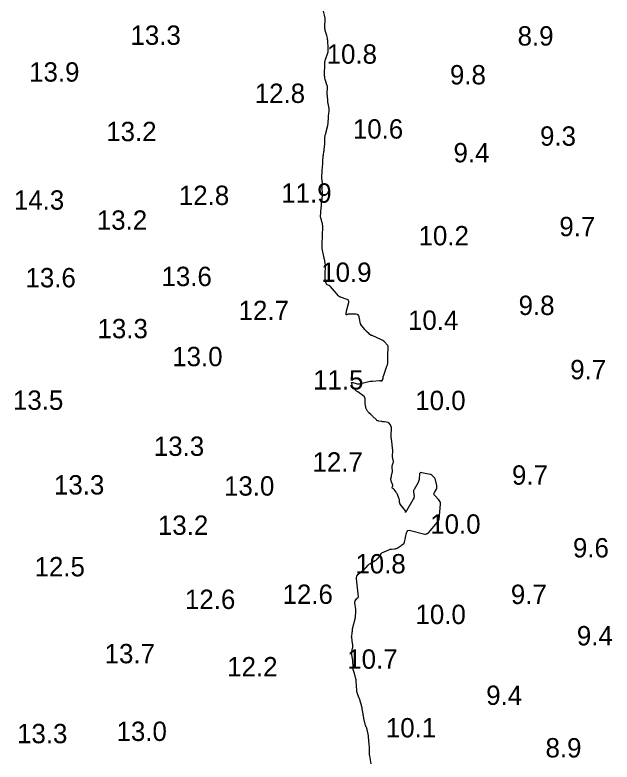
# Model space of a CAD drawing. Extents: x 815352 to 820877, y 582403 to 597439.
# Drawn here: x 820644.3 to 820798.6, y 590619.8 to 590813 of the extents above; entities that cross this region are included whole.
import ezdxf

# ---------------------------------------------------------------- set-up
doc = ezdxf.new("R2010")
doc.units = 0
doc.layers.add('V-CONT-EL12', color=7, linetype='Continuous')
doc.layers.add('V-TOPO-SOUN', color=7, linetype='Continuous')

msp = doc.modelspace()

# ---------------------------------------------------------------- linework, layer by layer
at = {"layer": 'V-CONT-EL12'}
msp.add_lwpolyline([(820736.39, 590619.34), (820735.98, 590621.46), (820735.95, 590621.62), (820735.93, 590621.77), (820735.92, 590621.93), (820735.92, 590622.08), (820735.92, 590622.71), (820735.92, 590622.86), (820735.91, 590623.02), (820735.91, 590623.17), (820735.9, 590623.33), (820735.8, 590624.67), (820735.78, 590624.87), (820735.77, 590625.07), (820735.75, 590625.27), (820735.74, 590625.47), (820735.67, 590626.26), (820735.65, 590626.46), (820735.63, 590626.65), (820735.6, 590626.85), (820735.56, 590627.04), (820735.34, 590628.15), (820735.31, 590628.25), (820735.28, 590628.35), (820735.25, 590628.45), (820735.21, 590628.55), (820735.04, 590628.93), (820735, 590629.03), (820734.97, 590629.12), (820734.94, 590629.22), (820734.91, 590629.32), (820734.49, 590631.05), (820734.42, 590631.35), (820734.35, 590631.65), (820734.3, 590631.95), (820734.24, 590632.26), (820734.03, 590633.59), (820733.99, 590633.83), (820733.94, 590634.08), (820733.89, 590634.32), (820733.83, 590634.55), (820733.55, 590635.57), (820733.49, 590635.78), (820733.43, 590635.98), (820733.36, 590636.18), (820733.28, 590636.38), (820732.86, 590637.43), (820732.83, 590637.5), (820732.81, 590637.57), (820732.78, 590637.64), (820732.76, 590637.72), (820732.67, 590638.01), (820732.65, 590638.09), (820732.64, 590638.16), (820732.62, 590638.24), (820732.62, 590638.32), (820732.47, 590640.7), (820732.47, 590640.76), (820732.47, 590640.81), (820732.46, 590640.87), (820732.46, 590640.92), (820732.44, 590641.14), (820732.44, 590641.2), (820732.43, 590641.25), (820732.42, 590641.31), (820732.41, 590641.36), (820732.21, 590642.12), (820732.17, 590642.27), (820732.13, 590642.41), (820732.08, 590642.55), (820732.04, 590642.69), (820731.76, 590643.53), (820731.74, 590643.62), (820731.72, 590643.71), (820731.71, 590643.8), (820731.7, 590643.9), (820731.69, 590644.27), (820731.69, 590644.37), (820731.68, 590644.46), (820731.68, 590644.55), (820731.67, 590644.65), (820731.61, 590645.83), (820731.59, 590646.03), (820731.57, 590646.23), (820731.55, 590646.43), (820731.51, 590646.63), (820731.35, 590647.52), (820731.32, 590647.67), (820731.31, 590647.82), (820731.31, 590647.97), (820731.33, 590648.12), (820731.42, 590648.92), (820731.43, 590648.98), (820731.44, 590649.03), (820731.46, 590649.09), (820731.49, 590649.14), (820731.6, 590649.35), (820731.62, 590649.41), (820731.63, 590649.46), (820731.64, 590649.52), (820731.64, 590649.58), (820731.59, 590650.05), (820731.58, 590650.15), (820731.57, 590650.25), (820731.56, 590650.35), (820731.54, 590650.45), (820731.32, 590652.01), (820731.3, 590652.14), (820731.3, 590652.27), (820731.31, 590652.4), (820731.33, 590652.53), (820731.43, 590653.07), (820731.45, 590653.2), (820731.47, 590653.32), (820731.48, 590653.45), (820731.49, 590653.57), (820731.53, 590654.08), (820731.54, 590654.21), (820731.56, 590654.33), (820731.58, 590654.46), (820731.61, 590654.58), (820732.2, 590656.85), (820732.24, 590657.05), (820732.28, 590657.24), (820732.3, 590657.44), (820732.32, 590657.64), (820732.37, 590658.43), (820732.37, 590658.63), (820732.37, 590658.83), (820732.36, 590659.03), (820732.35, 590659.23), (820732.14, 590661.02), (820732.14, 590661.14), (820732.15, 590661.25), (820732.19, 590661.37), (820732.24, 590661.47), (820732.57, 590662), (820732.61, 590662.05), (820732.65, 590662.1), (820732.7, 590662.14), (820732.75, 590662.18), (820732.96, 590662.32), (820733, 590662.36), (820733.03, 590662.41), (820733.05, 590662.46), (820733.05, 590662.52), (820732.54, 590667.23), (820732.55, 590667.57), (820732.62, 590667.87), (820732.78, 590668.14), (820733.01, 590668.37), (820734.27, 590669.4), (820734.45, 590669.55), (820734.63, 590669.71), (820734.8, 590669.88), (820734.96, 590670.04), (820735.61, 590670.73), (820735.77, 590670.9), (820735.95, 590671.05), (820736.14, 590671.19), (820736.34, 590671.31), (820737.39, 590671.91), (820737.54, 590672.01), (820737.69, 590672.12), (820737.83, 590672.24), (820737.96, 590672.37), (820738.58, 590673.06), (820738.63, 590673.13), (820738.68, 590673.2), (820738.73, 590673.28), (820738.77, 590673.36), (820738.92, 590673.69), (820738.96, 590673.76), (820739.01, 590673.83), (820739.08, 590673.88), (820739.15, 590673.92), (820740.93, 590674.73), (820741.1, 590674.79), (820741.28, 590674.84), (820741.46, 590674.88), (820741.64, 590674.9), (820742.38, 590674.93), (820742.57, 590674.95), (820742.74, 590675), (820742.91, 590675.06), (820743.07, 590675.15), (820744.15, 590675.85), (820744.23, 590675.9), (820744.31, 590675.96), (820744.39, 590676.02), (820744.47, 590676.08), (820744.77, 590676.33), (820744.84, 590676.4), (820744.9, 590676.48), (820744.94, 590676.56), (820744.97, 590676.65), (820745.49, 590679.06), (820745.62, 590679.42), (820745.84, 590679.65), (820746.15, 590679.75), (820746.53, 590679.7), (820750.19, 590678.76), (820750.24, 590678.76), (820750.28, 590678.75), (820750.33, 590678.76), (820750.38, 590678.76), (820750.62, 590678.83), (820750.64, 590678.83), (820750.65, 590678.84), (820750.67, 590678.84), (820750.69, 590678.84), (820750.76, 590678.85), (820750.78, 590678.86), (820750.8, 590678.86), (820750.82, 590678.87), (820750.83, 590678.88), (820751.03, 590678.99), (820751.06, 590679.01), (820751.1, 590679.04), (820751.13, 590679.07), (820751.16, 590679.1), (820753.52, 590681.87), (820753.55, 590681.9), (820753.58, 590681.93), (820753.6, 590681.97), (820753.63, 590682), (820753.73, 590682.15), (820753.75, 590682.18), (820753.76, 590682.22), (820753.78, 590682.25), (820753.8, 590682.28), (820753.87, 590682.41), (820753.89, 590682.45), (820753.9, 590682.48), (820753.91, 590682.52), (820753.91, 590682.55), (820754.26, 590686.48), (820754.26, 590686.81), (820754.19, 590687.11), (820754.05, 590687.39), (820753.85, 590687.65), (820752.78, 590688.76), (820752.65, 590688.94), (820752.59, 590689.13), (820752.61, 590689.33), (820752.7, 590689.54), (820753.2, 590690.38), (820753.3, 590690.59), (820753.36, 590690.81), (820753.37, 590691.04), (820753.34, 590691.28), (820752.98, 590692.78), (820752.93, 590692.93), (820752.87, 590693.07), (820752.79, 590693.19), (820752.69, 590693.32), (820752.11, 590693.94), (820752.08, 590693.97), (820752.04, 590694), (820752, 590694.03), (820751.97, 590694.05), (820751.8, 590694.14), (820751.76, 590694.16), (820751.72, 590694.18), (820751.68, 590694.19), (820751.63, 590694.2), (820749.41, 590694.63), (820749.17, 590694.64), (820749, 590694.57), (820748.89, 590694.42), (820748.85, 590694.19), (820748.8, 590693.11), (820748.77, 590692.85), (820748.71, 590692.59), (820748.62, 590692.34), (820748.5, 590692.1), (820747.43, 590690.32), (820747.36, 590690.18), (820747.32, 590690.03), (820747.3, 590689.88), (820747.31, 590689.73), (820747.41, 590688.95), (820747.42, 590688.87), (820747.42, 590688.78), (820747.43, 590688.7), (820747.43, 590688.61), (820747.42, 590688.23), (820747.42, 590688.17), (820747.4, 590688.11), (820747.38, 590688.06), (820747.36, 590688.01), (820747.23, 590687.8), (820747.2, 590687.75), (820747.17, 590687.69), (820747.14, 590687.64), (820747.11, 590687.59), (820745.5, 590684.8), (820745.43, 590684.69), (820745.36, 590684.58), (820745.28, 590684.48), (820745.19, 590684.38), (820745.26, 590684.48), (820745.28, 590684.57), (820745.27, 590684.68), (820745.21, 590684.78), (820743.89, 590686.47), (820743.82, 590686.58), (820743.76, 590686.7), (820743.72, 590686.82), (820743.7, 590686.95), (820743.66, 590687.49), (820743.64, 590687.62), (820743.61, 590687.75), (820743.58, 590687.88), (820743.53, 590688.01), (820743.13, 590689.02), (820743.06, 590689.17), (820742.99, 590689.31), (820742.9, 590689.45), (820742.81, 590689.59), (820742.28, 590690.29), (820742.24, 590690.33), (820742.21, 590690.36), (820742.17, 590690.39), (820742.13, 590690.42), (820741.94, 590690.53), (820741.91, 590690.55), (820741.88, 590690.58), (820741.86, 590690.61), (820741.84, 590690.65), (820741.78, 590690.81), (820741.77, 590690.85), (820741.77, 590690.89), (820741.78, 590690.92), (820741.79, 590690.96), (820741.91, 590691.18), (820741.93, 590691.22), (820741.94, 590691.27), (820741.94, 590691.32), (820741.93, 590691.38), (820741.52, 590692.45), (820741.48, 590692.59), (820741.46, 590692.74), (820741.45, 590692.88), (820741.47, 590693.03), (820741.57, 590693.68), (820741.6, 590693.8), (820741.62, 590693.93), (820741.65, 590694.05), (820741.68, 590694.18), (820741.8, 590694.67), (820741.83, 590694.79), (820741.84, 590694.92), (820741.85, 590695.04), (820741.84, 590695.17), (820741.75, 590695.83), (820741.74, 590695.98), (820741.75, 590696.13), (820741.77, 590696.28), (820741.81, 590696.43), (820742.06, 590697.2), (820742.1, 590697.35), (820742.11, 590697.5), (820742.11, 590697.64), (820742.08, 590697.79), (820741.93, 590698.39), (820741.9, 590698.54), (820741.88, 590698.69), (820741.87, 590698.84), (820741.87, 590699), (820741.92, 590700.19), (820741.92, 590700.34), (820741.92, 590700.48), (820741.92, 590700.62), (820741.9, 590700.77), (820741.84, 590701.34), (820741.82, 590701.48), (820741.8, 590701.62), (820741.79, 590701.77), (820741.77, 590701.91), (820741.57, 590703.4), (820741.54, 590703.67), (820741.52, 590703.95), (820741.52, 590704.22), (820741.53, 590704.5), (820741.62, 590705.96), (820741.62, 590706.06), (820741.61, 590706.15), (820741.6, 590706.25), (820741.57, 590706.35), (820741.46, 590706.73), (820741.43, 590706.82), (820741.38, 590706.91), (820741.33, 590707), (820741.27, 590707.08), (820740.99, 590707.42), (820740.92, 590707.5), (820740.83, 590707.55), (820740.74, 590707.59), (820740.64, 590707.62), (820739.77, 590707.74), (820739.59, 590707.77), (820739.41, 590707.8), (820739.23, 590707.82), (820739.05, 590707.85), (820738.32, 590707.96), (820738.14, 590708), (820737.98, 590708.07), (820737.83, 590708.16), (820737.69, 590708.27), (820736.7, 590709.26), (820736.59, 590709.37), (820736.47, 590709.48), (820736.35, 590709.59), (820736.24, 590709.69), (820735.73, 590710.13), (820735.63, 590710.22), (820735.54, 590710.32), (820735.46, 590710.43), (820735.39, 590710.55), (820735.12, 590711.02), (820735.05, 590711.14), (820735.01, 590711.27), (820734.97, 590711.4), (820734.95, 590711.53), (820734.84, 590712.41), (820734.82, 590712.56), (820734.81, 590712.7), (820734.8, 590712.85), (820734.79, 590712.99), (820734.76, 590713.77), (820734.76, 590713.82), (820734.75, 590713.87), (820734.75, 590713.91), (820734.73, 590713.96), (820734.68, 590714.14), (820734.66, 590714.19), (820734.64, 590714.22), (820734.61, 590714.26), (820734.58, 590714.29), (820732.87, 590715.5), (820732.74, 590715.6), (820732.6, 590715.7), (820732.47, 590715.81), (820732.34, 590715.92), (820731.84, 590716.37), (820731.73, 590716.49), (820731.63, 590716.62), (820731.56, 590716.77), (820731.51, 590716.92), (820731.32, 590717.69), (820731.3, 590717.84), (820731.34, 590717.93), (820731.44, 590717.97), (820731.59, 590717.94), (820732.49, 590717.65), (820732.71, 590717.6), (820732.92, 590717.58), (820733.13, 590717.59), (820733.35, 590717.62), (820735.41, 590718.12), (820735.73, 590718.19), (820736.05, 590718.25), (820736.37, 590718.29), (820736.7, 590718.32), (820738.54, 590718.43), (820738.6, 590718.43), (820738.66, 590718.42), (820738.72, 590718.42), (820738.79, 590718.4), (820739.03, 590718.34), (820739.09, 590718.34), (820739.14, 590718.35), (820739.18, 590718.38), (820739.21, 590718.43), (820739.35, 590718.72), (820739.38, 590718.78), (820739.4, 590718.85), (820739.42, 590718.93), (820739.42, 590719), (820739.45, 590719.3), (820739.46, 590719.37), (820739.47, 590719.45), (820739.49, 590719.52), (820739.51, 590719.59), (820740.43, 590722.14), (820740.54, 590722.52), (820740.63, 590722.91), (820740.68, 590723.3), (820740.7, 590723.7), (820740.7, 590725.8), (820740.7, 590725.96), (820740.71, 590726.11), (820740.72, 590726.27), (820740.73, 590726.43), (820740.78, 590727.07), (820740.78, 590727.22), (820740.74, 590727.36), (820740.68, 590727.49), (820740.58, 590727.61), (820739.78, 590728.46), (820739.6, 590728.62), (820739.41, 590728.77), (820739.21, 590728.9), (820738.99, 590729.01), (820736.6, 590730.06), (820736.57, 590730.07), (820736.54, 590730.08), (820736.51, 590730.09), (820736.48, 590730.09), (820736.35, 590730.11), (820736.32, 590730.11), (820736.29, 590730.12), (820736.26, 590730.14), (820736.24, 590730.15), (820735.99, 590730.35), (820735.94, 590730.39), (820735.89, 590730.43), (820735.84, 590730.47), (820735.8, 590730.52), (820735.16, 590731.16), (820735.04, 590731.28), (820734.92, 590731.41), (820734.81, 590731.53), (820734.7, 590731.66), (820734.02, 590732.48), (820733.98, 590732.54), (820733.94, 590732.59), (820733.9, 590732.64), (820733.86, 590732.69), (820733.7, 590732.91), (820733.67, 590732.96), (820733.64, 590733.02), (820733.62, 590733.08), (820733.6, 590733.15), (820733.26, 590734.93), (820733.17, 590735.21), (820733.01, 590735.42), (820732.79, 590735.54), (820732.49, 590735.58), (820730.53, 590735.61), (820730.46, 590735.61), (820730.39, 590735.6), (820730.33, 590735.58), (820730.27, 590735.56), (820730.02, 590735.45), (820729.97, 590735.44), (820729.93, 590735.45), (820729.91, 590735.48), (820729.91, 590735.54), (820729.93, 590736.04), (820729.94, 590736.15), (820729.95, 590736.26), (820729.97, 590736.36), (820729.99, 590736.46), (820730.55, 590738.61), (820730.58, 590738.89), (820730.52, 590739.11), (820730.37, 590739.29), (820730.13, 590739.41), (820728.45, 590740.02), (820728.42, 590740.02), (820728.4, 590740.03), (820728.38, 590740.04), (820728.35, 590740.05), (820728.26, 590740.08), (820728.23, 590740.09), (820728.21, 590740.1), (820728.19, 590740.11), (820728.17, 590740.13), (820728.03, 590740.22), (820728, 590740.24), (820727.97, 590740.26), (820727.95, 590740.29), (820727.92, 590740.31), (820725.83, 590742.72), (820725.74, 590742.81), (820725.65, 590742.89), (820725.55, 590742.96), (820725.45, 590743.02), (820725.01, 590743.23), (820724.91, 590743.3), (820724.83, 590743.37), (820724.77, 590743.47), (820724.72, 590743.58), (820724.51, 590744.25), (820724.47, 590744.4), (820724.44, 590744.56), (820724.42, 590744.71), (820724.42, 590744.87), (820724.43, 590745.66), (820724.43, 590745.85), (820724.44, 590746.03), (820724.45, 590746.22), (820724.47, 590746.4), (820724.56, 590747.49), (820724.58, 590747.69), (820724.58, 590747.88), (820724.56, 590748.08), (820724.54, 590748.28), (820724.39, 590749.27), (820724.37, 590749.37), (820724.35, 590749.47), (820724.33, 590749.57), (820724.31, 590749.67), (820724.22, 590750.08), (820724.19, 590750.18), (820724.17, 590750.28), (820724.15, 590750.38), (820724.13, 590750.48), (820723.72, 590752.55), (820723.7, 590752.65), (820723.69, 590752.74), (820723.68, 590752.84), (820723.67, 590752.93), (820723.66, 590753.31), (820723.65, 590753.41), (820723.65, 590753.5), (820723.65, 590753.6), (820723.66, 590753.69), (820723.82, 590758.21), (820723.82, 590758.48), (820723.8, 590758.74), (820723.75, 590759.01), (820723.69, 590759.26), (820723.31, 590760.55), (820723.27, 590760.68), (820723.25, 590760.81), (820723.25, 590760.94), (820723.25, 590761.08), (820723.3, 590761.61), (820723.31, 590761.75), (820723.32, 590761.88), (820723.33, 590762.02), (820723.34, 590762.15), (820723.5, 590763.78), (820723.51, 590763.91), (820723.52, 590764.05), (820723.54, 590764.18), (820723.55, 590764.32), (820723.62, 590764.86), (820723.63, 590765), (820723.65, 590765.13), (820723.66, 590765.27), (820723.67, 590765.4), (820723.73, 590766.38), (820723.74, 590766.56), (820723.75, 590766.75), (820723.75, 590766.94), (820723.74, 590767.12), (820723.71, 590767.86), (820723.7, 590768.05), (820723.7, 590768.24), (820723.7, 590768.42), (820723.71, 590768.61), (820723.74, 590769.37), (820723.74, 590769.55), (820723.74, 590769.74), (820723.72, 590769.92), (820723.7, 590770.1), (820723.58, 590770.89), (820723.56, 590771.04), (820723.56, 590771.2), (820723.56, 590771.35), (820723.57, 590771.5), (820723.64, 590772.11), (820723.66, 590772.26), (820723.68, 590772.41), (820723.69, 590772.56), (820723.71, 590772.71), (820723.86, 590774.44), (820723.87, 590774.64), (820723.88, 590774.84), (820723.89, 590775.04), (820723.89, 590775.24), (820723.9, 590776.35), (820723.91, 590776.4), (820723.91, 590776.46), (820723.92, 590776.51), (820723.94, 590776.57), (820724.01, 590776.78), (820724.02, 590776.84), (820724.04, 590776.89), (820724.05, 590776.95), (820724.06, 590777), (820724.13, 590777.5), (820724.14, 590777.61), (820724.15, 590777.71), (820724.17, 590777.81), (820724.18, 590777.92), (820724.3, 590779.03), (820724.32, 590779.18), (820724.33, 590779.34), (820724.34, 590779.49), (820724.34, 590779.64), (820724.35, 590780.27), (820724.35, 590780.42), (820724.36, 590780.56), (820724.37, 590780.71), (820724.37, 590780.85), (820724.41, 590781.44), (820724.43, 590781.58), (820724.45, 590781.72), (820724.47, 590781.87), (820724.51, 590782.01), (820725.11, 590784.41), (820725.16, 590784.62), (820725.2, 590784.84), (820725.23, 590785.06), (820725.24, 590785.28), (820725.29, 590786.21), (820725.3, 590786.41), (820725.31, 590786.6), (820725.33, 590786.79), (820725.35, 590786.98), (820725.47, 590788.01), (820725.47, 590788.07), (820725.48, 590788.13), (820725.48, 590788.2), (820725.49, 590788.26), (820725.5, 590788.52), (820725.5, 590788.58), (820725.5, 590788.65), (820725.49, 590788.71), (820725.48, 590788.77), (820725.23, 590790.05), (820725.19, 590790.29), (820725.15, 590790.52), (820725.13, 590790.76), (820725.11, 590791), (820724.99, 590792.67), (820724.98, 590792.79), (820724.98, 590792.92), (820724.98, 590793.05), (820724.99, 590793.17), (820725.05, 590793.81), (820725.05, 590793.87), (820725.05, 590793.94), (820725.05, 590794), (820725.05, 590794.07), (820725.04, 590794.33), (820725.04, 590794.4), (820725.03, 590794.46), (820725.02, 590794.53), (820725, 590794.59), (820724.48, 590796.31), (820724.4, 590796.62), (820724.35, 590796.94), (820724.32, 590797.25), (820724.31, 590797.57), (820724.33, 590800.14), (820724.35, 590800.47), (820724.39, 590800.8), (820724.46, 590801.12), (820724.56, 590801.44), (820725.15, 590803.16), (820725.18, 590803.25), (820725.2, 590803.34), (820725.21, 590803.43), (820725.22, 590803.53), (820725.24, 590803.9), (820725.24, 590804), (820725.24, 590804.09), (820725.24, 590804.19), (820725.23, 590804.28), (820725.13, 590806.32), (820725.1, 590806.64), (820725.05, 590806.96), (820724.98, 590807.28), (820724.9, 590807.6), (820724.5, 590808.91), (820724.43, 590809.19), (820724.38, 590809.48), (820724.36, 590809.78), (820724.37, 590810.07), (820724.48, 590811.65), (820724.49, 590811.76), (820724.48, 590811.86), (820724.47, 590811.97), (820724.45, 590812.07), (820724.36, 590812.49), (820724.34, 590812.59), (820724.31, 590812.69), (820724.29, 590812.8), (820724.27, 590812.9), (820724.07, 590813.92)], dxfattribs=at)

# ---------------------------------------------------------------- texts
at = {"layer": 'V-TOPO-SOUN'}
for s, p in [('13.3 ', (820674.13, 590805.23)), ('8.9', (820774.21, 590805.04)), ('10.8 ', (820724.85, 590800.35)), ('13.9 ', (820647.92, 590795.72)), ('9.8', (820756.72, 590795)), ('12.8 ', (820706.25, 590790.21)), ('13.2 ', (820667.86, 590780.33)), ('10.6 ', (820731.62, 590780.99)), ('9.3', (820780.01, 590779.15)), ('9.4', (820757.64, 590774.85)), ('12.8 ', (820686.63, 590763.83)), ('11.9 ', (820713.11, 590764.42)), ('14.3 ', (820643.98, 590762.62)), ('13.2 ', (820665.43, 590757.43)), ('9.7', (820785, 590755.76)), ('10.2 ', (820748.6, 590753.4)), ('13.6 ', (820646.98, 590742.54)), ('13.6 ', (820682.15, 590742.87)), ('10.9 ', (820723.44, 590743.95)), ('9.8', (820774.47, 590735.39)), ('12.7 ', (820702.08, 590734.07)), ('10.4 ', (820745.88, 590731.55)), ('13.3 ', (820665.6, 590729.38)), ('13.0 ', (820684.92, 590722.16)), ('9.7', (820787.82, 590718.78)), ('11.5 ', (820721.34, 590716.13)), ('13.5 ', (820643.75, 590710.88)), ('10.0 ', (820747.75, 590710.81)), ('13.3 ', (820680.17, 590698.97)), ('12.7 ', (820721.18, 590694.9)), ('9.7', (820772.76, 590691.52)), ('13.3 ', (820654.35, 590688.99)), ('13.0 ', (820698.31, 590688.7)), ('10.0 ', (820751.62, 590678.86)), ('13.2 ', (820681.22, 590678.56)), ('9.6', (820788.52, 590672.72)), ('12.5 ', (820649.33, 590667.83)), ('10.8 ', (820732.27, 590668.59)), ('12.6 ', (820713.44, 590660.71)), ('9.7', (820772.47, 590660.68)), ('12.6 ', (820688.22, 590659.4)), ('10.0 ', (820747.81, 590655.5)), ('9.4', (820789.53, 590649.99)), ('13.7 ', (820667.44, 590645.36)), ('10.7 ', (820730.17, 590643.95)), ('12.2 ', (820699.13, 590641.98)), ('9.4', (820766.1, 590634.6)), ('13.3 ', (820644.8, 590624.69)), ('13.0 ', (820670.52, 590625.28)), ('10.1 ', (820740.15, 590626.2)), ('8.9', (820781.43, 590621.02))]:
    msp.add_text(s, height=5, dxfattribs=at).set_placement(p)

doc.saveas('drawing.dxf')
